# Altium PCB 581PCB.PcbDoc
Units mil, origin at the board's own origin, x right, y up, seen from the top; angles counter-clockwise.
Board outline 3824.43 x 3537.72 mil, 4 copper layers (Top Layer, Mid Layer 1, Mid Layer 2, Bottom Layer), stack 23.756 mil thick; 5 components, 19 nets, 44 pads, 42 vias.
Unrouted connection lines stored in the file: 9.
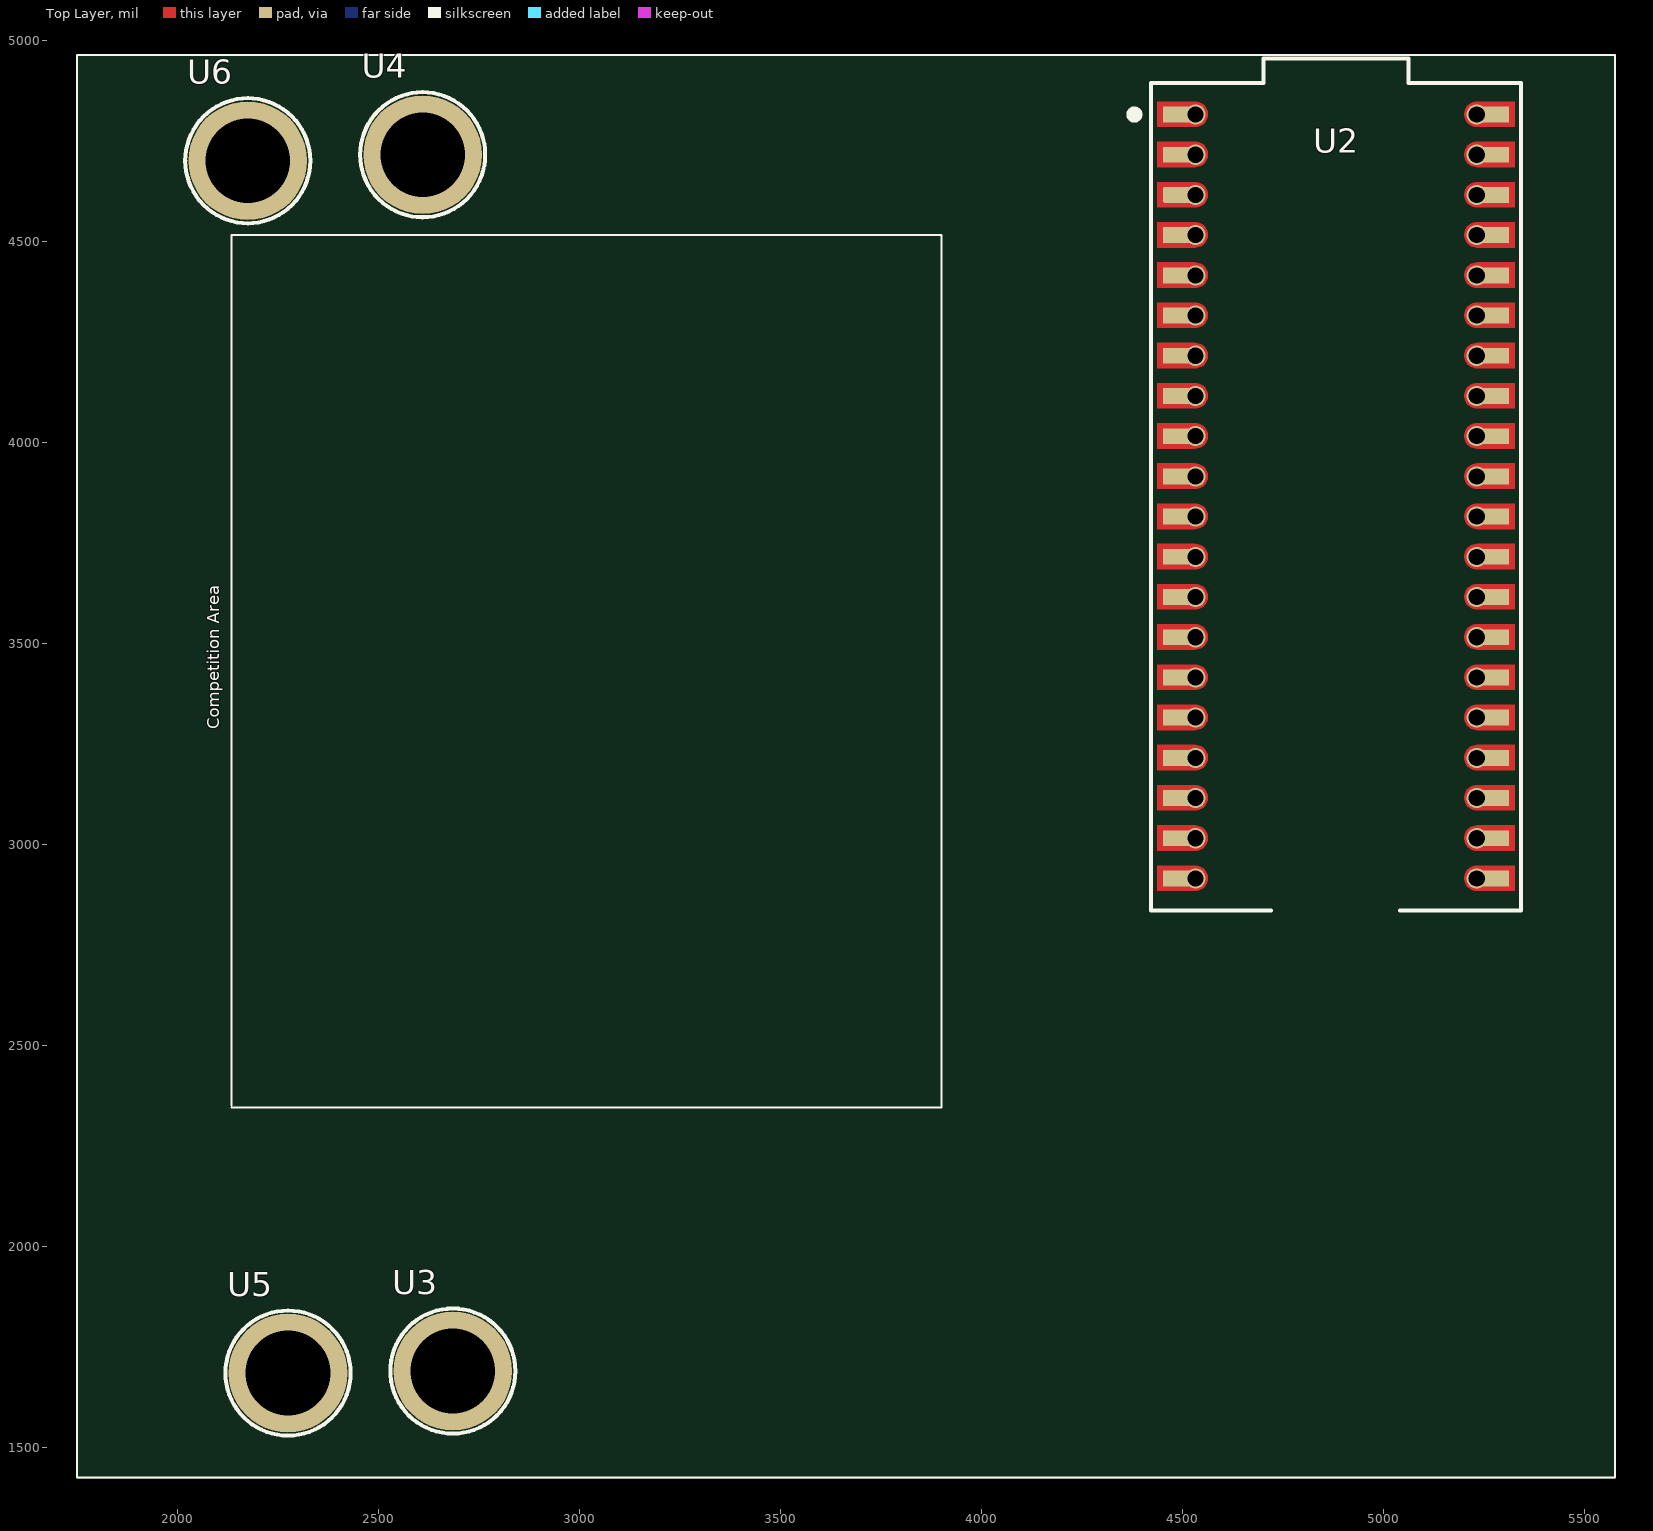
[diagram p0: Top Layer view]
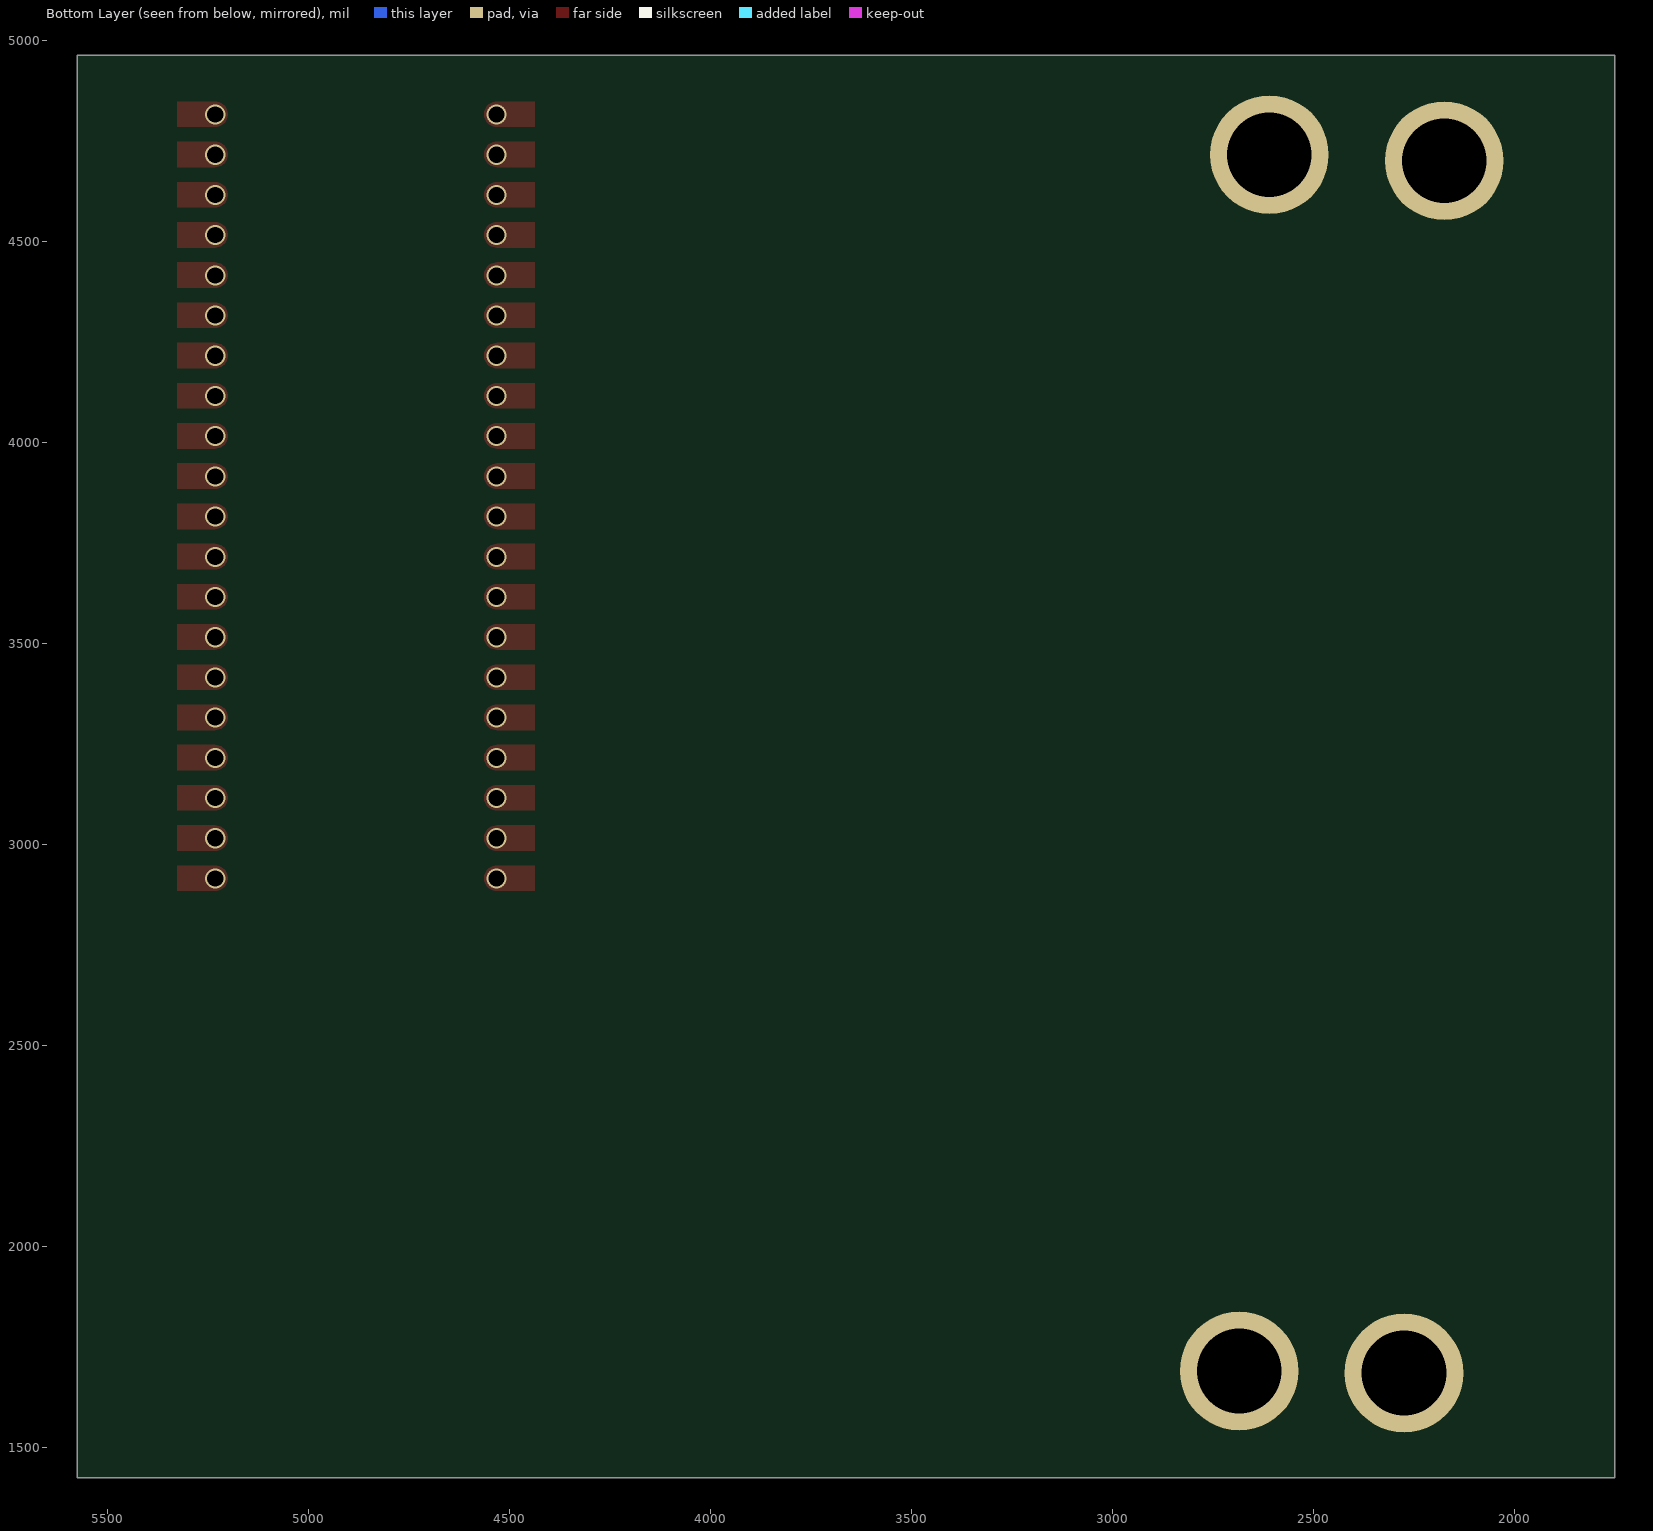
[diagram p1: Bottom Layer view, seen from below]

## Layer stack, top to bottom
Top Solder: solder mask 0.4, Solder Resist, Dk 3.5
Top Layer: signal copper 1.4
Dielectric 2: prepreg 2.8, PP-006, Dk 4.1
Mid Layer 1: signal copper 1.378
Dielectric 1: dielectric 12.6, FR-4, Dk 4.8
Mid Layer 2: signal copper 1.378
Dielectric 3: prepreg 2.8, PP-006, Dk 4.1
Bottom Layer: signal copper 1.4
Bottom Solder: solder mask 0.4, Solder Resist, Dk 3.5

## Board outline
1750.57,2797.72 1750.57,4962.72 5575,4962.72 5575,1425 1750.57,1425

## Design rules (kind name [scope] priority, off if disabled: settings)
Clearance [All] p1: gap=10 ignorepadtopadclearanceinfootprint=FALSE except(0: Arc-Hole Track-Hole SMDPad-Hole THPad-Hole Via-Hole Fill-Hole Poly-Hole Region-Hole Text-Hole)
PolygonConnect [All] p1: connectstyle=Relief reliefconductorwidth=10 reliefentries=4 polygonreliefangle="90 Angle" airgapwidth=10
RoutingVias [All] p1: holewidth=28 width=50 viastyle="Through Hole" minholewidth=28 minwidth=50 maxholewidth=28 maxwidth=50
SolderMaskExpansion [All] p1: expansion=4 istentingtop=FALSE
Width [All] p1: maxlimit=10 minlimit=10 preferedwidth=10
30 further rules are at their usual default settings.

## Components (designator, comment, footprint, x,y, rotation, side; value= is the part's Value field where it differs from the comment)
U2 "RPI-PICO-581Socket" RPI-PICO-MOD 4881.5,3853.78 r0 top
U3 "Banana Jack" "Banana Jack" 2685,1690 r0 top
U4 "Banana Jack" "Banana Jack" 2610,4715 r0 top
U5 "Banana Jack" "Banana Jack" 2275,1685 r0 top
U6 "Banana Jack" "Banana Jack" 2175,4700 r0 top

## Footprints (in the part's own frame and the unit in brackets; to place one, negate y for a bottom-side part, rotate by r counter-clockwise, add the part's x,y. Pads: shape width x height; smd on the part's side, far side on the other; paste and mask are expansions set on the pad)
"Banana Jack" [mm] "575-8"
  round 7.5 hole 5.35: 1(0,0)
  silkscreen extent -3.95,-3.95 3.95,3.95, body extent -3.93,-3.95 3.94,3.94, height 9
RPI-PICO-MOD [mm] "RASPBERRY PI PICO RP2040 BOARD"
  rect 2.5x1 smd mask+0.102: 1(-9.69,24.415) 2(-9.69,21.875) 4(-9.69,16.795) 5(-9.69,14.255) 6(-9.69,11.715) 7(-9.69,9.175) 8(-9.69,6.635) 9(-9.69,4.095) 10(-9.69,1.555) 11(-9.69,-0.985) 12(-9.69,-3.525) 13(-9.69,-6.065) 14(-9.69,-8.605) 15(-9.69,-11.145) 16(-9.69,-13.685) 17(-9.69,-16.225) 18(-9.69,-18.765) 19(-9.69,-21.305) 20(-9.69,-23.845)
  rrect25% 2.5x1 smd mask+0.102: 3(-9.69,19.335)
  rect 2.5x1 smd: 21(9.69,-23.845) 22(9.69,-21.305) 23(9.69,-18.765) 24(9.69,-16.225) 25(9.69,-13.685) 26(9.69,-11.145) 27(9.69,-8.605) 28(9.69,-6.065) 29(9.69,-3.525) 30(9.69,-0.985) 31(9.69,1.555) 32(9.69,4.095) 33(9.69,6.635) 34(9.69,9.175) 35(9.69,11.715) 36(9.69,14.255) 37(9.69,16.795) 38(9.69,19.335) 39(9.69,21.875) 40(9.69,24.415)
  Top Layer region: -11.292,-24.629 -11.292,-23.029 -8.892,-23.029 -8.892,-23.029 -8.545,-23.108 -8.267,-23.33 -8.112,-23.651 -8.112,-24.007 -8.267,-24.328 -8.545,-24.55 -8.892,-24.629 -8.892,-24.629
  Top Layer region: -11.292,-22.089 -11.292,-20.489 -8.892,-20.489 -8.892,-20.489 -8.545,-20.568 -8.267,-20.79 -8.112,-21.111 -8.112,-21.467 -8.267,-21.788 -8.545,-22.01 -8.892,-22.089 -8.892,-22.089
  Top Layer region: -11.292,-19.549 -11.292,-17.949 -8.892,-17.949 -8.892,-17.949 -8.545,-18.028 -8.267,-18.25 -8.112,-18.571 -8.112,-18.927 -8.267,-19.248 -8.545,-19.47 -8.892,-19.549 -8.892,-19.549
  Top Layer region: -11.292,-17.009 -11.292,-15.409 -8.892,-15.409 -8.892,-15.409 -8.545,-15.488 -8.267,-15.71 -8.112,-16.031 -8.112,-16.387 -8.267,-16.708 -8.545,-16.93 -8.892,-17.009 -8.892,-17.009
  Top Layer region: -11.292,-14.469 -11.292,-12.869 -8.892,-12.869 -8.892,-12.869 -8.545,-12.948 -8.267,-13.17 -8.112,-13.491 -8.112,-13.847 -8.267,-14.168 -8.545,-14.39 -8.892,-14.469 -8.892,-14.469
  Top Layer region: -11.292,-11.929 -11.292,-10.329 -8.892,-10.329 -8.892,-10.329 -8.545,-10.408 -8.267,-10.63 -8.112,-10.951 -8.112,-11.307 -8.267,-11.628 -8.545,-11.85 -8.892,-11.929 -8.892,-11.929
  Top Layer region: -11.292,-9.389 -11.292,-7.789 -8.892,-7.789 -8.892,-7.789 -8.545,-7.868 -8.267,-8.09 -8.112,-8.411 -8.112,-8.767 -8.267,-9.088 -8.545,-9.31 -8.892,-9.389 -8.892,-9.389
  Top Layer region: -11.292,-6.849 -11.292,-5.249 -8.892,-5.249 -8.892,-5.249 -8.545,-5.328 -8.267,-5.55 -8.112,-5.871 -8.112,-6.227 -8.267,-6.548 -8.545,-6.77 -8.892,-6.849 -8.892,-6.849
  Top Layer region: -11.292,-4.309 -11.292,-2.709 -8.892,-2.709 -8.892,-2.709 -8.545,-2.788 -8.267,-3.01 -8.112,-3.331 -8.112,-3.687 -8.267,-4.008 -8.545,-4.23 -8.892,-4.309 -8.892,-4.309
  Top Layer region: -11.292,-1.769 -11.292,-0.169 -8.892,-0.169 -8.892,-0.169 -8.545,-0.248 -8.267,-0.47 -8.112,-0.791 -8.112,-1.147 -8.267,-1.468 -8.545,-1.69 -8.892,-1.769 -8.892,-1.769
  Top Layer region: -11.292,0.771 -11.292,2.371 -8.892,2.371 -8.892,2.371 -8.545,2.292 -8.267,2.07 -8.112,1.749 -8.112,1.393 -8.267,1.072 -8.545,0.85 -8.892,0.771 -8.892,0.771
  Top Layer region: -11.292,3.311 -11.292,4.911 -8.892,4.911 -8.892,4.911 -8.545,4.832 -8.267,4.61 -8.112,4.289 -8.112,3.933 -8.267,3.612 -8.545,3.39 -8.892,3.311 -8.892,3.311
  Top Layer region: -11.292,5.851 -11.292,7.451 -8.892,7.451 -8.892,7.451 -8.545,7.372 -8.267,7.15 -8.112,6.829 -8.112,6.473 -8.267,6.152 -8.545,5.93 -8.892,5.851 -8.892,5.851
  Top Layer region: -11.292,8.391 -11.292,9.991 -8.892,9.991 -8.892,9.991 -8.545,9.912 -8.267,9.69 -8.112,9.369 -8.112,9.013 -8.267,8.692 -8.545,8.47 -8.892,8.391 -8.892,8.391
  Top Layer region: -11.292,10.931 -11.292,12.531 -8.892,12.531 -8.892,12.531 -8.545,12.452 -8.267,12.23 -8.112,11.909 -8.112,11.553 -8.267,11.232 -8.545,11.01 -8.892,10.931 -8.892,10.931
  Top Layer region: -11.292,13.471 -11.292,15.071 -8.892,15.071 -8.892,15.071 -8.545,14.992 -8.267,14.77 -8.112,14.449 -8.112,14.093 -8.267,13.772 -8.545,13.55 -8.892,13.471 -8.892,13.471
  Top Layer region: -11.292,16.011 -11.292,17.611 -8.892,17.611 -8.892,17.611 -8.545,17.532 -8.267,17.31 -8.112,16.989 -8.112,16.633 -8.267,16.312 -8.545,16.09 -8.892,16.011 -8.892,16.011
  Top Layer region: -11.292,18.551 -11.292,20.151 -8.892,20.151 -8.892,20.151 -8.545,20.072 -8.267,19.85 -8.112,19.529 -8.112,19.173 -8.267,18.852 -8.545,18.63 -8.892,18.551 -8.892,18.551
  Top Layer region: -11.292,21.091 -11.292,22.691 -8.892,22.691 -8.892,22.691 -8.545,22.612 -8.267,22.39 -8.112,22.069 -8.112,21.713 -8.267,21.392 -8.545,21.17 -8.892,21.091 -8.892,21.091
  Top Layer region: -11.292,23.631 -11.292,25.231 -8.892,25.231 -8.892,25.231 -8.545,25.152 -8.267,24.93 -8.112,24.609 -8.112,24.253 -8.267,23.932 -8.545,23.71 -8.892,23.631 -8.892,23.631
  Top Layer region: 11.292,23.631 11.292,25.231 8.892,25.231 8.892,25.231 8.545,25.152 8.267,24.93 8.112,24.609 8.112,24.253 8.267,23.932 8.545,23.71 8.892,23.631 8.892,23.631
  Top Layer region: 11.292,21.091 11.292,22.691 8.892,22.691 8.892,22.691 8.545,22.612 8.267,22.39 8.112,22.069 8.112,21.713 8.267,21.392 8.545,21.17 8.892,21.091 8.892,21.091
  Top Layer region: 11.292,18.551 11.292,20.151 8.892,20.151 8.892,20.151 8.545,20.072 8.267,19.85 8.112,19.529 8.112,19.173 8.267,18.852 8.545,18.63 8.892,18.551 8.892,18.551
  Top Layer region: 11.292,16.011 11.292,17.611 8.892,17.611 8.892,17.611 8.545,17.532 8.267,17.31 8.112,16.989 8.112,16.633 8.267,16.312 8.545,16.09 8.892,16.011 8.892,16.011
  Top Layer region: 11.292,13.471 11.292,15.071 8.892,15.071 8.892,15.071 8.545,14.992 8.267,14.77 8.112,14.449 8.112,14.093 8.267,13.772 8.545,13.55 8.892,13.471 8.892,13.471
  Top Layer region: 11.292,10.931 11.292,12.531 8.892,12.531 8.892,12.531 8.545,12.452 8.267,12.23 8.112,11.909 8.112,11.553 8.267,11.232 8.545,11.01 8.892,10.931 8.892,10.931
  Top Layer region: 11.292,8.391 11.292,9.991 8.892,9.991 8.892,9.991 8.545,9.912 8.267,9.69 8.112,9.369 8.112,9.013 8.267,8.692 8.545,8.47 8.892,8.391 8.892,8.391
  Top Layer region: 11.292,5.851 11.292,7.451 8.892,7.451 8.892,7.451 8.545,7.372 8.267,7.15 8.112,6.829 8.112,6.473 8.267,6.152 8.545,5.93 8.892,5.851 8.892,5.851
  Top Layer region: 11.292,3.311 11.292,4.911 8.892,4.911 8.892,4.911 8.545,4.832 8.267,4.61 8.112,4.289 8.112,3.933 8.267,3.612 8.545,3.39 8.892,3.311 8.892,3.311
  Top Layer region: 11.292,0.771 11.292,2.371 8.892,2.371 8.892,2.371 8.545,2.292 8.267,2.07 8.112,1.749 8.112,1.393 8.267,1.072 8.545,0.85 8.892,0.771 8.892,0.771
  Top Layer region: 11.292,-1.769 11.292,-0.169 8.892,-0.169 8.892,-0.169 8.545,-0.248 8.267,-0.47 8.112,-0.791 8.112,-1.147 8.267,-1.468 8.545,-1.69 8.892,-1.769 8.892,-1.769
  Top Layer region: 11.292,-4.309 11.292,-2.709 8.892,-2.709 8.892,-2.709 8.545,-2.788 8.267,-3.01 8.112,-3.331 8.112,-3.687 8.267,-4.008 8.545,-4.23 8.892,-4.309 8.892,-4.309
  Top Layer region: 11.292,-6.849 11.292,-5.249 8.892,-5.249 8.892,-5.249 8.545,-5.328 8.267,-5.55 8.112,-5.871 8.112,-6.227 8.267,-6.548 8.545,-6.77 8.892,-6.849 8.892,-6.849
  Top Layer region: 11.292,-9.389 11.292,-7.789 8.892,-7.789 8.892,-7.789 8.545,-7.868 8.267,-8.09 8.112,-8.411 8.112,-8.767 8.267,-9.088 8.545,-9.31 8.892,-9.389 8.892,-9.389
  Top Layer region: 11.292,-11.929 11.292,-10.329 8.892,-10.329 8.892,-10.329 8.545,-10.408 8.267,-10.63 8.112,-10.951 8.112,-11.307 8.267,-11.628 8.545,-11.85 8.892,-11.929 8.892,-11.929
  Top Layer region: 11.292,-14.469 11.292,-12.869 8.892,-12.869 8.892,-12.869 8.545,-12.948 8.267,-13.17 8.112,-13.491 8.112,-13.847 8.267,-14.168 8.545,-14.39 8.892,-14.469 8.892,-14.469
  Top Layer region: 11.292,-17.009 11.292,-15.409 8.892,-15.409 8.892,-15.409 8.545,-15.488 8.267,-15.71 8.112,-16.031 8.112,-16.387 8.267,-16.708 8.545,-16.93 8.892,-17.009 8.892,-17.009
  Top Layer region: 11.292,-19.549 11.292,-17.949 8.892,-17.949 8.892,-17.949 8.545,-18.028 8.267,-18.25 8.112,-18.571 8.112,-18.927 8.267,-19.248 8.545,-19.47 8.892,-19.549 8.892,-19.549
  Top Layer region: 11.292,-22.089 11.292,-20.489 8.892,-20.489 8.892,-20.489 8.545,-20.568 8.267,-20.79 8.112,-21.111 8.112,-21.467 8.267,-21.788 8.545,-22.01 8.892,-22.089 8.892,-22.089
  Top Layer region: 11.292,-24.629 11.292,-23.029 8.892,-23.029 8.892,-23.029 8.545,-23.108 8.267,-23.33 8.112,-23.651 8.112,-24.007 8.267,-24.328 8.545,-24.55 8.892,-24.629 8.892,-24.629
  silkscreen extent -12.99,-25.88 11.68,27.94, body extent -10.49,-25.21 10.51,27.22, height 3.69

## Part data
U2: "RASPBERRY PI PICO RP2040 BOARD", Manufacturer="Raspberry Pi Foundation", Manufacturer Part No=SC0915, Supplier Part Number 1=S7053-ND
U3 U4 U5 U6: "575-8", Supplier Part Number 1=36-575-8-ND

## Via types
v1: diameter 50, hole 40, Top Layer to Bottom Layer, 42 vias

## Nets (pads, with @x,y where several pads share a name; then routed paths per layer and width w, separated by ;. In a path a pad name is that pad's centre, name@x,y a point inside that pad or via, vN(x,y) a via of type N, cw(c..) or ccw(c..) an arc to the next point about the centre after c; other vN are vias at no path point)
1V: U4.1
48V: U3.1
GND: U2.3 U2.8 U2.13 U2.18 U2.23 U2.28 U2.33 U2.38 U5.1 U6.1
  other v1: 4531.5,3115 5231.5,3115 4531.5,3615 5231.5,3615 4531.5,4115 5231.5,4115 4531.5,4615 5231.5,4615
PWM0: U2.1
  other v1: 4531.5,4815 4531.5,4815
PWM1: U2.4
  other v1: 4531.5,4515
PWM2: U2.6
  other v1: 4531.5,4315
PWM3: U2.9
  other v1: 4531.5,4015
PWM4: U2.11
  other v1: 4531.5,3815
PWM5: U2.14
  other v1: 4531.5,3515
PWM6: U2.16
  other v1: 4531.5,3315
PWM7: U2.19
  other v1: 4531.5,3015
~PWM0: U2.2
  other v1: 4531.5,4715
~PWM1: U2.5
  other v1: 4531.5,4415
~PWM2: U2.7
  other v1: 4531.5,4215
~PWM3: U2.10
  other v1: 4531.5,3915
~PWM4: U2.12
  other v1: 4531.5,3715
~PWM5: U2.15
  other v1: 4531.5,3415
~PWM6: U2.17
  other v1: 4531.5,3215
~PWM7: U2.20
  other v1: 4531.5,2915
pads on no net: U2.21 U2.22 U2.24 U2.25 U2.26 U2.27 U2.29 U2.30 U2.31 U2.32 U2.34 U2.35 U2.36 U2.37 U2.39 U2.40
copper on no net:
  other v1: 5231.5,2915 5231.5,3015 5231.5,3215 5231.5,3315 5231.5,3415 5231.5,3515 5231.5,3715 5231.5,3815 5231.5,3915 5231.5,4015 5231.5,4215 5231.5,4315 5231.5,4415 5231.5,4515 5231.5,4715 5231.5,4815 5231.5,4815

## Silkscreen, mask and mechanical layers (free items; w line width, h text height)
Top Overlay:
  lines w5: 2135,2345 3900,2345 3900,4515 2135,4515 2135,2350 ; 1750.57,1425 1750.57,2797.72 1750.57,4962.72 5575,4962.72 5575,1425 1750.57,1425
  text "Competition Area" at 2104,3286 h30 r90

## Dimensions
2135,2350 to 3900,2345 on Top Overlay
3900,4515 to 3900,2345 on Top Overlay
